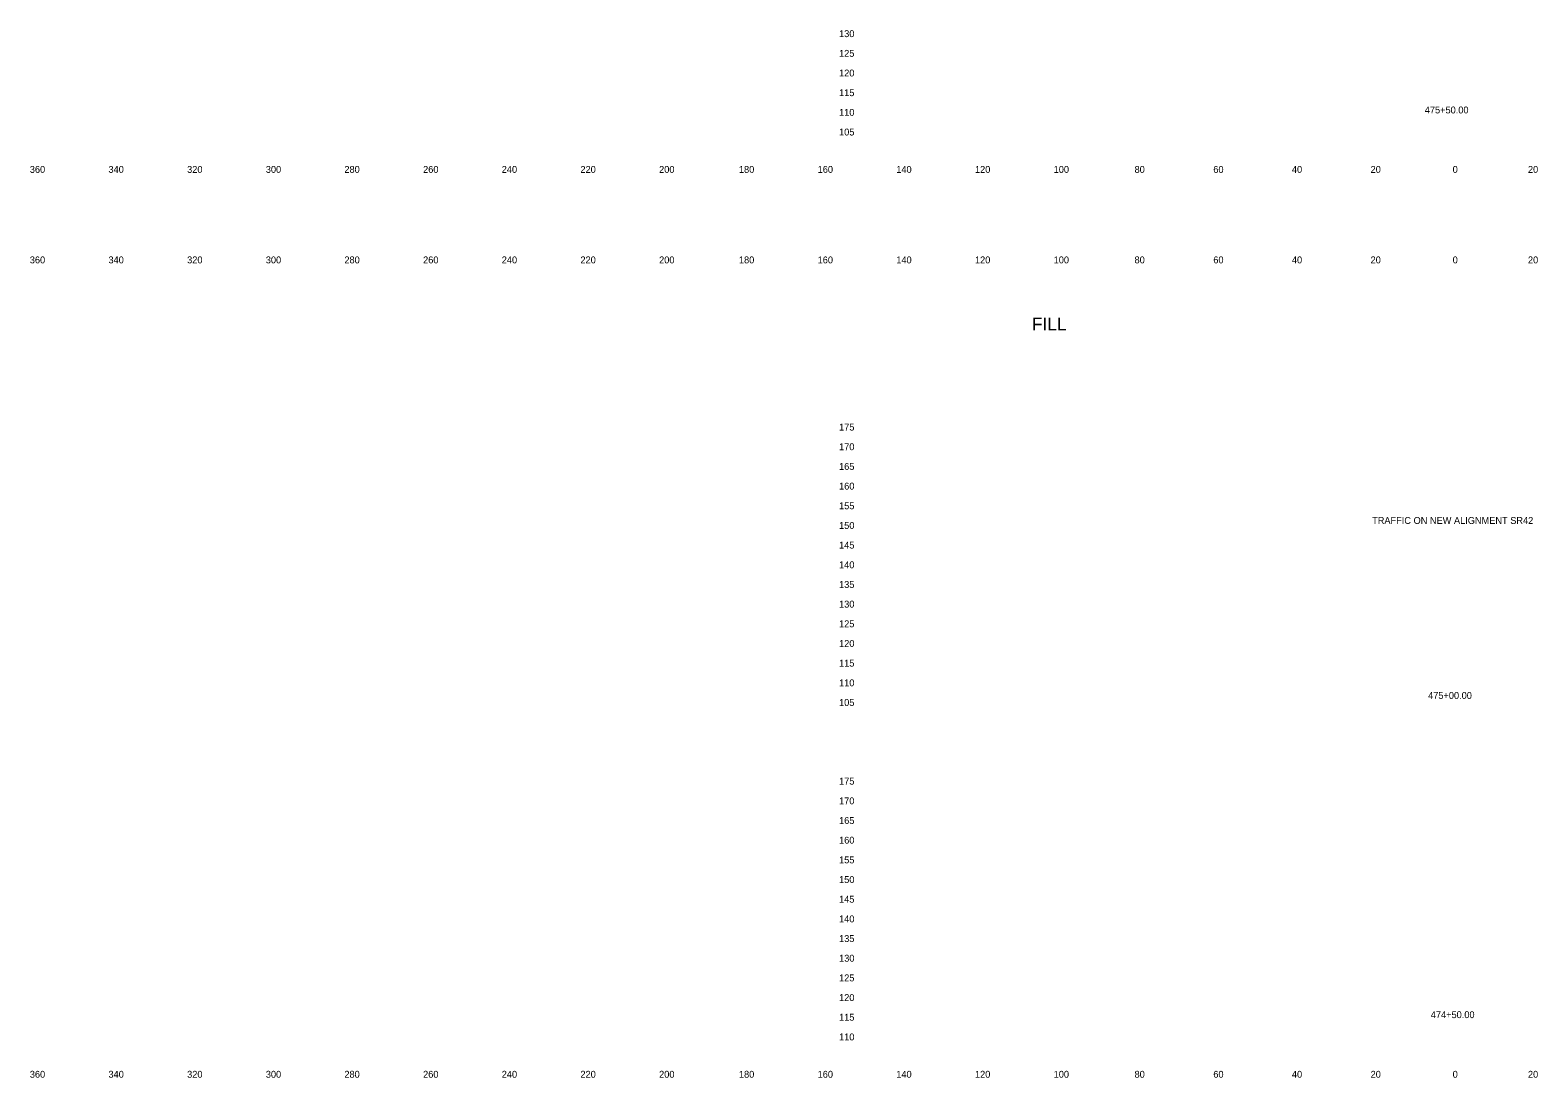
# Model space of a CAD drawing. Extents: x 21281 to 22024, y 6472 to 15208.
# Drawn here: x 21280.5 to 21663.8, y 10845.3 to 11111.6 of the extents above; entities that cross this region are included whole.
import ezdxf

# ---------------------------------------------------------------- set-up
doc = ezdxf.new("R2010")
doc.units = 0
for name, color, linetype in [('XS_SHEET_LABELS_ELEVATION', 7, 'Continuous'), ('XS_SHEET_LABELS_OFFSET', 7, 'Continuous'), ('XS_SHEET_LABELS_STATION', 7, 'Continuous')]:
    doc.layers.add(name, color=color, linetype=linetype)

msp = doc.modelspace()

# ---------------------------------------------------------------- texts
at = {"layer": 'XS_SHEET_LABELS_ELEVATION'}
for s, p in [('  130  ', (21484.84, 11109.84)), ('  125  ', (21484.84, 11104.84)), ('  120  ', (21484.84, 11099.84)), ('  115  ', (21484.84, 11094.84)), ('  110  ', (21484.84, 11089.84)), ('  105  ', (21484.84, 11084.84)), ('  175  ', (21484.84, 11009.84)), ('  170  ', (21484.84, 11004.84)), ('  165  ', (21484.84, 10999.84)), ('  160  ', (21484.84, 10994.84)), ('  155  ', (21484.84, 10989.84)), ('  150  ', (21484.84, 10984.84)), ('  145  ', (21484.84, 10979.84)), ('  140  ', (21484.84, 10974.84)), ('  135  ', (21484.84, 10969.84)), ('  130  ', (21484.84, 10964.84)), ('  125  ', (21484.84, 10959.84)), ('  120  ', (21484.84, 10954.84)), ('  115  ', (21484.84, 10949.84)), ('  110  ', (21484.84, 10944.84)), ('  105  ', (21484.84, 10939.84)), ('  175  ', (21484.84, 10919.84)), ('  170  ', (21484.84, 10914.84)), ('  165  ', (21484.84, 10909.84)), ('  160  ', (21484.84, 10904.84)), ('  155  ', (21484.84, 10899.84)), ('  150  ', (21484.84, 10894.84)), ('  145  ', (21484.84, 10889.84)), ('  140  ', (21484.84, 10884.84)), ('  135  ', (21484.84, 10879.84)), ('  130  ', (21484.84, 10874.84)), ('  125  ', (21484.84, 10869.84)), ('  120  ', (21484.84, 10864.84)), ('  115  ', (21484.84, 10859.84)), ('  110  ', (21484.84, 10854.84))]:
    msp.add_text(s, height=1.75, dxfattribs=at).set_placement(p)
at = {"layer": 'XS_SHEET_LABELS_OFFSET'}
for s, height, p in [('  360  ', 1.75, (21279.14, 11075.34)), ('  340  ', 1.75, (21299.13, 11075.34)), ('  320  ', 1.75, (21319.13, 11075.34)), ('  300  ', 1.75, (21339.13, 11075.34)), ('  280  ', 1.75, (21359.1, 11075.34)), ('  260  ', 1.75, (21379.11, 11075.34)), ('  240  ', 1.75, (21399.1, 11075.34)), ('  220  ', 1.75, (21419.1, 11075.34)), ('  200  ', 1.75, (21439.1, 11075.34)), ('  180  ', 1.75, (21459.39, 11075.34)), ('  160  ', 1.75, (21479.4, 11075.34)), ('  140  ', 1.75, (21499.39, 11075.34)), ('  120  ', 1.75, (21519.39, 11075.34)), ('  100  ', 1.75, (21539.39, 11075.34)), ('  80  ', 1.75, (21559.95, 11075.34)), ('  60  ', 1.75, (21579.97, 11075.34)), ('  40  ', 1.75, (21599.95, 11075.34)), ('  20  ', 1.75, (21619.95, 11075.34)), ('  0  ', 1.75, (21640.81, 11075.34)), ('  0  ', 1.75, (21640.81, 11075.34)), ('  20  ', 1.75, (21659.95, 11075.34)), ('  360  ', 1.75, (21279.14, 11052.34)), ('  340  ', 1.75, (21299.13, 11052.34)), ('  320  ', 1.75, (21319.13, 11052.34)), ('  300  ', 1.75, (21339.13, 11052.34)), ('  280  ', 1.75, (21359.1, 11052.34)), ('  260  ', 1.75, (21379.11, 11052.34)), ('  240  ', 1.75, (21399.1, 11052.34)), ('  220  ', 1.75, (21419.1, 11052.34)), ('  200  ', 1.75, (21439.1, 11052.34)), ('  180  ', 1.75, (21459.39, 11052.34)), ('  160  ', 1.75, (21479.4, 11052.34)), ('  140  ', 1.75, (21499.39, 11052.34)), ('  120  ', 1.75, (21519.39, 11052.34)), ('  100  ', 1.75, (21539.39, 11052.34)), ('  80  ', 1.75, (21559.95, 11052.34)), ('  60  ', 1.75, (21579.97, 11052.34)), ('  40  ', 1.75, (21599.95, 11052.34)), ('  20  ', 1.75, (21619.95, 11052.34)), ('  0  ', 1.75, (21640.81, 11052.34)), ('  0  ', 1.75, (21640.81, 11052.34)), ('  20  ', 1.75, (21659.95, 11052.34)), ('FILL', 3.273, (21535.18, 11035.29)), ('  360  ', 1.75, (21279.14, 10845.34)), ('  340  ', 1.75, (21299.13, 10845.34)), ('  320  ', 1.75, (21319.13, 10845.34)), ('  300  ', 1.75, (21339.13, 10845.34)), ('  280  ', 1.75, (21359.1, 10845.34)), ('  260  ', 1.75, (21379.11, 10845.34)), ('  240  ', 1.75, (21399.1, 10845.34)), ('  220  ', 1.75, (21419.1, 10845.34)), ('  200  ', 1.75, (21439.1, 10845.34)), ('  180  ', 1.75, (21459.39, 10845.34)), ('  160  ', 1.75, (21479.4, 10845.34)), ('  140  ', 1.75, (21499.39, 10845.34)), ('  120  ', 1.75, (21519.39, 10845.34)), ('  100  ', 1.75, (21539.39, 10845.34)), ('  80  ', 1.75, (21559.95, 10845.34)), ('  60  ', 1.75, (21579.97, 10845.34)), ('  40  ', 1.75, (21599.95, 10845.34)), ('  20  ', 1.75, (21619.95, 10845.34)), ('  0  ', 1.75, (21640.81, 10845.34)), ('  0  ', 1.75, (21640.81, 10845.34)), ('  20  ', 1.75, (21659.95, 10845.34))]:
    msp.add_text(s, height=height, dxfattribs=at).set_placement(p)
at = {"layer": 'XS_SHEET_LABELS_STATION'}
for s, p in [('  475+50.00  ', (21633.72, 11090.45)), ('TRAFFIC ON NEW ALIGNMENT SR42', (21621.64, 10986.11)), ('  475+00.00  ', (21634.57, 10941.63)), ('  474+50.00  ', (21635.25, 10860.49))]:
    msp.add_text(s, height=1.75, dxfattribs=at).set_placement(p)

doc.saveas('drawing.dxf')
